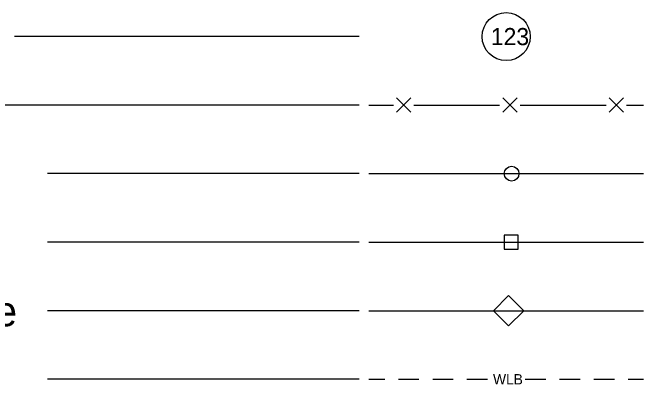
# Model space of a CAD drawing. Extents: x 1552903 to 1553044, y 811448 to 811540.
# Drawn here: x 1552920.46 to 1552935.92, y 811507.49 to 811516.61 of the extents above; entities that cross this region are included whole.
import ezdxf

# ---------------------------------------------------------------- set-up
doc = ezdxf.new("R2010")
doc.units = 0
doc.layers.add('Exist DTM Breakline', color=7, linetype='Continuous')

msp = doc.modelspace()

# ---------------------------------------------------------------- linework, layer by layer
at = {"layer": 'Exist DTM Breakline'}
for p, q in [((1552928.953, 811516.022), (1552920.504, 811516.022)), ((1552929.867, 811514.164), (1552930.221, 811514.517)), ((1552930.221, 811514.164), (1552929.867, 811514.517)), ((1552932.474, 811514.164), (1552932.827, 811514.517)), ((1552932.827, 811514.164), (1552932.474, 811514.517)), ((1552935.08, 811514.164), (1552935.433, 811514.517)), ((1552935.433, 811514.164), (1552935.08, 811514.517)), ((1552928.953, 811514.341), (1552916.752, 811514.341)), ((1552929.195, 811514.341), (1552929.792, 811514.341)), ((1552930.296, 811514.341), (1552931.347, 811514.341)), ((1552931.347, 811514.341), (1552932.398, 811514.341)), ((1552932.903, 811514.341), (1552933.954, 811514.341)), ((1552933.954, 811514.341), (1552935.005, 811514.341)), ((1552935.509, 811514.341), (1552935.921, 811514.341)), ((1552928.953, 811512.659), (1552921.316, 811512.659)), ((1552929.195, 811512.659), (1552935.921, 811512.659)), ((1552929.195, 811512.659), (1552935.921, 811512.659)), ((1552928.953, 811510.978), (1552921.316, 811510.978)), ((1552929.195, 811510.978), (1552935.921, 811510.978)), ((1552929.195, 811510.978), (1552935.921, 811510.978)), ((1552928.953, 811509.296), (1552921.316, 811509.296)), ((1552929.195, 811509.296), (1552935.921, 811509.296)), ((1552929.195, 811509.296), (1552935.921, 811509.296)), ((1552928.953, 811507.614), (1552921.316, 811507.614)), ((1552929.195, 811507.614), (1552929.58, 811507.614)), ((1552929.916, 811507.614), (1552930.42, 811507.614)), ((1552930.757, 811507.614), (1552931.261, 811507.614)), ((1552931.597, 811507.614), (1552932.102, 811507.614)), ((1552933.027, 811507.614), (1552933.531, 811507.614)), ((1552933.868, 811507.614), (1552934.372, 811507.614)), ((1552934.708, 811507.614), (1552935.213, 811507.614)), ((1552935.549, 811507.614), (1552935.921, 811507.614))]:
    msp.add_line(p, q, dxfattribs=at)
for points in [[(1552932.505, 811510.805), (1552932.85, 811510.805), (1552932.85, 811511.15), (1552932.505, 811511.15)], [(1552932.617, 811508.926), (1552932.987, 811509.296), (1552932.617, 811509.67), (1552932.247, 811509.296)]]:
    msp.add_lwpolyline(points, close=True, dxfattribs=at)
for centre, radius in [((1552932.558, 811516.022), 0.589), ((1552932.69, 811512.659), 0.181)]:
    msp.add_circle(centre, radius, dxfattribs=at)

# ---------------------------------------------------------------- texts
for s, height, p in [('123', 0.4204, (1552932.182, 811515.812)), ('Proposed Barbed Wire Fence', 0.73569, (1552907.608, 811508.914)), ('WLB', 0.2522, (1552932.236, 811507.488))]:
    msp.add_text(s, height=height, dxfattribs=at).set_placement(p)

doc.saveas('drawing.dxf')
